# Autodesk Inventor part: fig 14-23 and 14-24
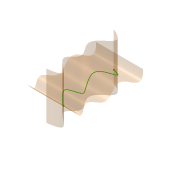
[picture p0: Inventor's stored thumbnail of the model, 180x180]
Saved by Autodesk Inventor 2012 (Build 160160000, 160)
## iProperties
Created: 2007-05
Part Number: fig 14-23 and 14-24
Document SubType Name: Modeling
Designer: Administrator
Density: 1 g/cm^3
Material: Default
Author: Administrator
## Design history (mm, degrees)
node "Sketch1"
node "Sketch2"
sketch "Sketch3"
  geometry: 7 further points
  constraints: 7 other
extrude_surface "ExtrusionSrf1" sketch "Sketch3" dims "d0" = 50, "d1" = 0
sketch "Sketch4"
  geometry: 7 further points
  constraints: 7 other
extrude_surface "ExtrusionSrf2" sketch "Sketch4" dims "d2" = 50, "d3" = 0
sketch "3D Sketch1"
  node "3D Intersection1"
body "Srf1"
body "Srf2"
